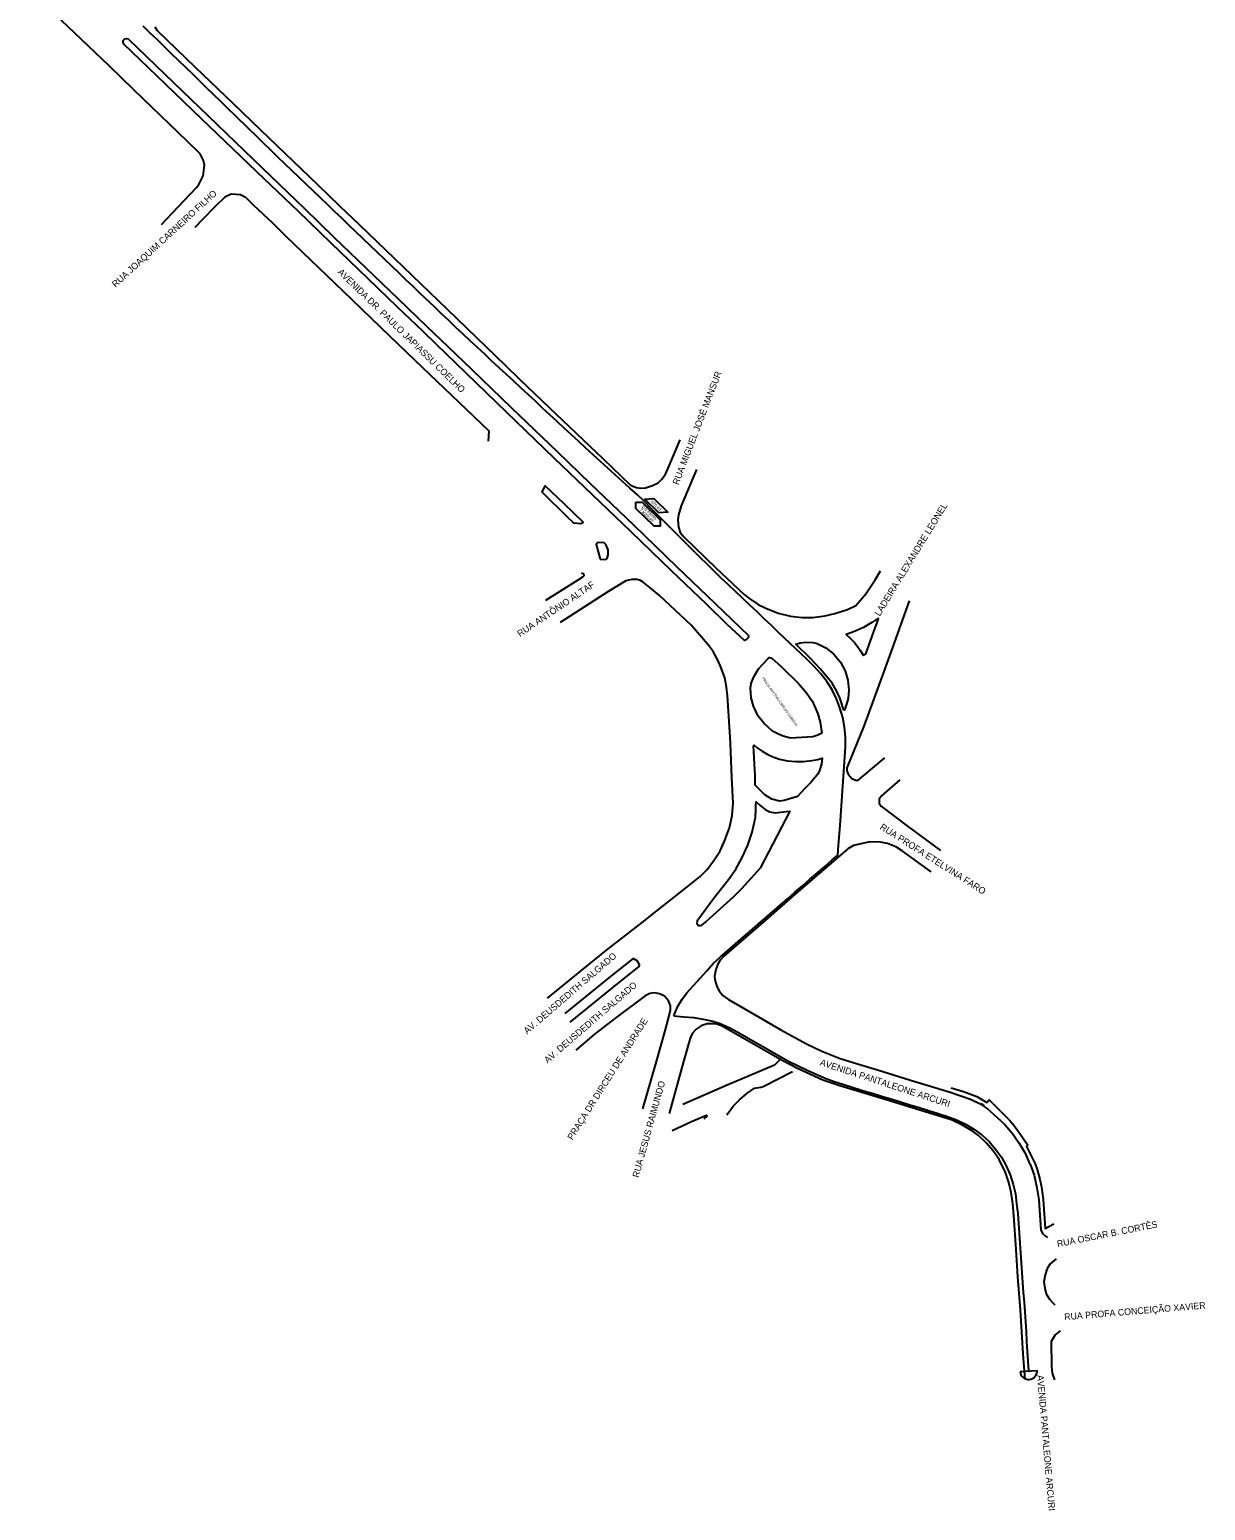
# Model space of a CAD drawing. Extents: x 656692 to 673945, y 7585994 to 7599066.
# Drawn here: x 665793 to 666966, y 7585994 to 7587471 of the extents above; entities that cross this region are included whole.
import ezdxf

# ---------------------------------------------------------------- set-up
doc = ezdxf.new("R2010")
doc.units = 0
for name, color, linetype in [('LOGRADOURO', 7, 'Continuous'), ('LOGRADOURO_TEXTO', 7, 'Continuous'), ('SIMBOLO', 7, 'Continuous'), ('TEXTO', 7, 'Continuous'), ('TUBO_PEAD_GN_63', 7, 'Continuous')]:
    doc.layers.add(name, color=color, linetype=linetype)

msp = doc.modelspace()

# ---------------------------------------------------------------- linework, layer by layer
at = {"layer": 'LOGRADOURO'}
msp.add_line((666745.5, 7586398), (666742.5, 7586400.4), dxfattribs=at)
for points in [[(665924.7, 7587277.2), (665941, 7587294.5), (665959.5, 7587314), (665962, 7587316.8), (665966.4, 7587325.6), (665967.4, 7587333.5), (665967.5, 7587336.3), (665966.7, 7587340.9), (665963.3, 7587347.4), (665950.2, 7587360.3), (665897.3, 7587411.2), (665872.5, 7587435.2), (665838.3, 7587467.8), (665793.2, 7587511.3)], [(665917.9, 7587474.3), (665920.1, 7587471), (665958.3, 7587434.1), (665995.7, 7587398.2), (666023.5, 7587371.5), (666080.2, 7587317), (666102.7, 7587295.4), (666122, 7587276.9), (666209.5, 7587192.5), (666267.8, 7587136.4), (666281.9, 7587122.8), (666311.7, 7587094.3), (666365.1, 7587043.2), (666392.3, 7587017.3), (666394.8, 7587015.9), (666398.5, 7587014.6), (666402.6, 7587014), (666407.3, 7587014.4), (666414.4, 7587016.8), (666420, 7587019.5), (666423.9, 7587023), (666427.3, 7587027.9), (666430.1, 7587034.1), (666442.1, 7587062.4)], [(665887, 7587457.1), (665886.2, 7587460.1), (665888.1, 7587462.4), (665890.2, 7587462.7), (665891.4, 7587462.1), (665928, 7587427), (665971.4, 7587385.3), (666025, 7587333.7), (666067.2, 7587293.1), (666096.7, 7587264.4), (666160.8, 7587203), (666189.4, 7587175.4), (666202.8, 7587162.7), (666234.2, 7587132.4), (666273.4, 7587094.5), (666319.7, 7587050.2), (666351.9, 7587019.2), (666395.4, 7586977.6), (666438.4, 7586935.9), (666477.1, 7586898.9), (666510.1, 7586867.1), (666510, 7586864.8), (666510, 7586864.8), (666508, 7586862.7), (666506.1, 7586862.2), (666489.3, 7586877.8), (666468.3, 7586898.3), (666433.3, 7586931.7), (666393.1, 7586970.4), (666347.1, 7587014.7), (666316.5, 7587044.1), (666269.3, 7587089.6), (666228.5, 7587128.9), (666198.9, 7587157.3), (666185.4, 7587170.7), (666160.2, 7587194.6), (666130.4, 7587223.3), (666093.8, 7587258.4), (666060.9, 7587290.3), (666027.4, 7587322.4), (665964.7, 7587382.4), (665920.2, 7587425.2), (665887, 7587457.1)], [(666250.8, 7587060.9), (666251.4, 7587070.9), (666207, 7587113.5), (666177.8, 7587141.3), (666143.9, 7587174), (666114.5, 7587202.3), (666049.1, 7587265.1), (666035.7, 7587278.3), (666016.8, 7587295.9), (666009.3, 7587303.8), (666003.6, 7587306.8), (665994.2, 7587307.3), (665987.8, 7587304.3), (665978.3, 7587295.1), (665965.9, 7587282.4), (665957.9, 7587274.1)], [(666458.4, 7587032.6), (666443.2, 7586996.4), (666440.5, 7586987.6), (666439.8, 7586982.5), (666440.4, 7586975.3), (666442, 7586970), (666446, 7586965.1), (666478, 7586934.2), (666506, 7586908), (666511.5, 7586903.6), (666519.9, 7586898), (666527.4, 7586894.3), (666539.8, 7586889.3), (666552, 7586886.4), (666563.6, 7586885), (666574.2, 7586885.1), (666586.4, 7586886.6), (666596.4, 7586888.9), (666609, 7586893), (666617.3, 7586897.1), (666627.1, 7586908.8), (666636.6, 7586922.6), (666641.9, 7586931.6)], [(666305.8, 7587008.6), (666304.4, 7587010.1), (666307.4, 7587016.4), (666326.1, 7586998.7), (666345.4, 7586980.1), (666343, 7586978.4), (666335.9, 7586979.2), (666329.1, 7586985.8), (666305.8, 7587008.6)], [(666362.3, 7586943.2), (666367.9, 7586943), (666369.3, 7586944), (666370.3, 7586947.6), (666370.3, 7586952.7), (666368, 7586958), (666366.1, 7586959.4), (666360, 7586959.7), (666358.3, 7586957.8), (666362.3, 7586943.2)], [(666340.2, 7586922.6), (666344.9, 7586925.7), (666346.2, 7586926.8), (666346, 7586928.3), (666343.5, 7586929.2)], [(666308.2, 7586902.3), (666340.2, 7586922.6), (666340.2, 7586922.6)], [(666309.6, 7586505.3), (666343.9, 7586533.3), (666368.7, 7586553.3), (666404, 7586580.8), (666418.7, 7586592.5), (666448.6, 7586616.1), (666461.9, 7586626.7), (666469.1, 7586633.7), (666476.4, 7586643.7), (666481.5, 7586651.7), (666486.3, 7586662), (666491.2, 7586675.2), (666493.9, 7586687.5), (666494.8, 7586700), (666493.6, 7586725.3), (666492.3, 7586759.6), (666490.5, 7586786.5), (666489.3, 7586806.8), (666488.3, 7586815.7), (666486.5, 7586825), (666482.4, 7586836.5), (666479.1, 7586843.7), (666474.8, 7586851.1), (666470, 7586857.8), (666453, 7586877.3), (666421.4, 7586907), (666411.9, 7586915.1), (666405, 7586920.3), (666401.8, 7586922.2), (666399.1, 7586922.8), (666393.9, 7586922.9), (666387.9, 7586921.6), (666370.9, 7586911.2), (666322.3, 7586880.1)], [(666670.3, 7586901.6), (666656.7, 7586863.4), (666645.2, 7586831.1), (666625.3, 7586776.6), (666608.4, 7586735.2), (666608.2, 7586732.2), (666609.7, 7586728.8), (666613.2, 7586724.6), (666617.1, 7586722.7), (666619.2, 7586722.6), (666625.6, 7586727.8), (666646.2, 7586745)], [(666624.9, 7586847), (666627.2, 7586848.9), (666634.8, 7586870.2), (666639.7, 7586883.8), (666639.1, 7586884.2), (666633.1, 7586880), (666624.9, 7586875.2), (666615.9, 7586871.2), (666607.5, 7586868.1), (666611.4, 7586864.8), (666616.2, 7586859.8), (666621.2, 7586852.8), (666624.9, 7586847)], [(666605.2, 7586792.6), (666601.2, 7586804.9), (666597.7, 7586812.5), (666593.6, 7586819.4), (666590.3, 7586823.7), (666581.7, 7586834), (666572.4, 7586843.7), (666557.3, 7586858.5), (666561.8, 7586859.9), (666567.4, 7586860.3), (666574.3, 7586860.2), (666578.6, 7586859.1), (666587.4, 7586854.7), (666595.1, 7586848.8), (666601.8, 7586840.6), (666606.5, 7586832), (666609.3, 7586822.5), (666610.3, 7586812.7), (666609.5, 7586804.4), (666608.1, 7586798.6), (666606, 7586792.6), (666605.2, 7586792.6)], [(666583.4, 7586769.6), (666579.5, 7586767.8), (666574.5, 7586766.1), (666552.1, 7586764.7), (666544.9, 7586766.7), (666540.2, 7586768.6), (666534.2, 7586771.8), (666525.7, 7586779.2), (666519.7, 7586786.8), (666515.1, 7586796.5), (666513, 7586805), (666512.1, 7586814.7), (666512.9, 7586819.2), (666515.4, 7586826), (666520.1, 7586833.9), (666529.5, 7586843.9), (666531.2, 7586845), (666533.6, 7586844.6), (666543.1, 7586835.7), (666560.1, 7586819.3), (666568.2, 7586810), (666574, 7586801.2), (666579.5, 7586789.1), (666581.6, 7586780.8), (666583.4, 7586769.6)], [(666515.2, 7586757.2), (666515.7, 7586757.7), (666519, 7586755.1), (666523.8, 7586751.7), (666529.4, 7586748.5), (666535.4, 7586745.8), (666541, 7586743.9), (666549, 7586742.2), (666557.3, 7586741.4), (666565.2, 7586741.3), (666573.3, 7586742.3), (666579.5, 7586743.5), (666583.7, 7586744.7), (666582.9, 7586738.7), (666580.6, 7586731.4), (666579.1, 7586728.4), (666572.3, 7586720.5), (666566.1, 7586714.3), (666559.1, 7586706.4), (666545.9, 7586702.6), (666541.1, 7586701.9), (666533.4, 7586704), (666526.6, 7586708.3), (666520.7, 7586713.9), (666516.9, 7586717.8), (666516.7, 7586727.1), (666515.2, 7586757.2)], [(666661, 7586723.1), (666642.7, 7586707.2), (666640.5, 7586703.8), (666640.5, 7586699.5), (666642.7, 7586696.6), (666668.9, 7586677), (666701.6, 7586652.6)], [(666462.4, 7586577.6), (666460.4, 7586577.5), (666458.9, 7586579.3), (666459.3, 7586582.4), (666459.7, 7586583.5), (666475.4, 7586604.8), (666490.2, 7586623.7), (666497.4, 7586634), (666503.8, 7586645.5), (666509.5, 7586658.1), (666513.7, 7586670.9), (666517.1, 7586685.7), (666517.6, 7586693.9), (666517.5, 7586698), (666517.8, 7586701.3), (666521.5, 7586698), (666526.9, 7586693.6), (666531.6, 7586691.2), (666536.7, 7586690.2), (666547.9, 7586691.5), (666551.4, 7586691.8), (666521.7, 7586635), (666521.7, 7586635), (666503.2, 7586614.3), (666494.9, 7586606.2), (666468, 7586581.8), (666462.4, 7586577.6)], [(666692.3, 7586631.5), (666663.5, 7586652.3), (666657.7, 7586656.1), (666648.7, 7586659.6), (666641.8, 7586660.9), (666631.2, 7586661.3), (666614.9, 7586657.7), (666609.3, 7586654.4), (666557.2, 7586609.5), (666527.3, 7586583.3), (666485.6, 7586547.2), (666481.9, 7586543.3), (666479.6, 7586539.4), (666477.6, 7586533.8), (666476.3, 7586527.4), (666476.5, 7586523.6), (666478.5, 7586516.9), (666480.9, 7586512.6), (666484.7, 7586508.1), (666490.3, 7586503.9), (666520.3, 7586486.6), (666542.6, 7586473.7), (666568.1, 7586459.9), (666583.4, 7586452.6), (666601.7, 7586445.1), (666618.9, 7586439.8), (666639, 7586433.7), (666671.8, 7586423.7), (666710.2, 7586411.9), (666731.6, 7586404.7), (666740.7, 7586400.3), (666748.6, 7586394.8), (666754.6, 7586389.6), (666765.8, 7586379.4), (666773.5, 7586370.4), (666780.3, 7586360.8), (666786.1, 7586350.9), (666790.2, 7586341.2), (666791.2, 7586339.7), (666795, 7586328.7), (666797.7, 7586316.2), (666799.7, 7586304.3), (666800.5, 7586293.9), (666801.9, 7586274.4), (666803.6, 7586270.5), (666806.5, 7586267.8), (666808.5, 7586266.5)], [(666332.3, 7586481.4), (666379.9, 7586520.1), (666399.6, 7586535.5), (666401.3, 7586537), (666401.5, 7586538.6), (666399.3, 7586542.6), (666395.3, 7586544.8), (666373, 7586527.3), (666326.9, 7586490)], [(666404.9, 7586394.9), (666418.5, 7586442.2), (666427, 7586472.7), (666432.4, 7586493), (666432.4, 7586497.6), (666430.5, 7586502.6), (666426.3, 7586507.2), (666421.3, 7586509.8), (666416.4, 7586510.7), (666411.7, 7586510), (666407.1, 7586507.8), (666378.2, 7586486.1), (666356.5, 7586469.3), (666337.9, 7586453.5)], [(666786.2, 7586125), (666784.3, 7586150.5), (666781.5, 7586194.4), (666779, 7586227.3), (666777.1, 7586254.7), (666774.8, 7586288.7), (666773.7, 7586300.1), (666772.2, 7586311.5), (666769.9, 7586321.4), (666766.5, 7586331.6), (666760.1, 7586344.4), (666753.9, 7586353.3), (666747.3, 7586361.2), (666739.6, 7586368.5), (666734.2, 7586372.2), (666723.7, 7586378.8), (666713.2, 7586383.5), (666707, 7586385.6), (666643.3, 7586405.3), (666601.4, 7586417.8), (666584.3, 7586423.7), (666567.6, 7586431.3), (666559.9, 7586435), (666544.5, 7586442.7), (666529.9, 7586451.1), (666483.2, 7586477.9), (666478.7, 7586479.5), (666475.2, 7586479.8), (666469.1, 7586479.6), (666463, 7586477.9), (666457.9, 7586474.3), (666454.4, 7586470.5), (666452.1, 7586465.5), (666445.4, 7586442.2), (666431, 7586390.4)], [(666541.4, 7586443.9), (666536, 7586438.6), (666489, 7586418.6), (666444.8, 7586399.4)], [(666488.7, 7586389.1), (666495, 7586397.6), (666501.1, 7586404.1), (666508.4, 7586410.2), (666516.1, 7586415.5), (666522.6, 7586416.5), (666524.7, 7586417.1), (666554.2, 7586432.2)], [(666712.4, 7586416), (666724.7, 7586412.1), (666738, 7586407.3), (666747.8, 7586401.2), (666750.2, 7586403.9), (666770.5, 7586383.6), (666775, 7586378.8), (666780.8, 7586370.3), (666788.8, 7586358.7), (666787.4, 7586357.4), (666796, 7586340.2), (666798.1, 7586334.5), (666800.7, 7586324.8), (666802.3, 7586316.7), (666804.1, 7586304.5), (666806.2, 7586275.7), (666814.6, 7586280.1)], [(666433.9, 7586373.5), (666453.4, 7586382.3), (666468.4, 7586388.8), (666469, 7586387.8), (666465.6, 7586384.6)], [(666817.2, 7586245.4), (666811.1, 7586240.4), (666808.2, 7586235.8), (666806, 7586229.5), (666804.9, 7586222.3), (666806, 7586214.2), (666807.3, 7586209.8), (666810.5, 7586205.1), (666813.6, 7586201.3), (666815.7, 7586199.3)], [(666821.1, 7586173.5), (666816, 7586169.5), (666812.2, 7586163), (666812.5, 7586138), (666813.1, 7586131.4), (666815.5, 7586124.6)]]:
    msp.add_lwpolyline(points, dxfattribs=at)
at = {"layer": 'SIMBOLO'}
msp.add_lwpolyline([(666397.9, 7587000.1), (666404.1, 7587000.2), (666422.1, 7586982.5), (666422.2, 7586976.3), (666416, 7586976.3), (666397.9, 7586993.9), (666397.9, 7587000.1)], dxfattribs=at)
msp.add_lwpolyline([(666420.6, 7586989.6), (666406.9, 7587003), (666415.9, 7587003.7), (666429.6, 7586990.2)], close=True, dxfattribs=at)
at = {"layer": 'TUBO_PEAD_GN_63'}
msp.add_line((666781.1, 7586133), (666798.1, 7586133.9), dxfattribs=at)
for points in [[(666599.4, 7586648.1), (666600.1, 7586657.9), (666601.5, 7586677.5), (666602.2, 7586687.3), (666602.9, 7586697.1), (666603.6, 7586707), (666604.3, 7586716.8), (666605, 7586726.6), (666606.4, 7586746.2), (666607, 7586756.1), (666607, 7586765.9), (666606, 7586775.7), (666604.2, 7586785.4), (666601.4, 7586794.8), (666597.9, 7586804), (666593.5, 7586812.8), (666588.3, 7586821.2), (666582.4, 7586829), (666575.8, 7586836.3), (666568.7, 7586843.1), (666540.2, 7586870.2), (666533, 7586877), (666525.9, 7586883.8), (666518.7, 7586890.6), (666511.6, 7586897.3), (666497.3, 7586910.9), (666490.2, 7586917.7), (666483, 7586924.4), (666475.9, 7586931.2), (666468.9, 7586938.1), (666461.9, 7586945), (666454.9, 7586951.9), (666447.9, 7586958.9), (666440.9, 7586965.8), (666433.9, 7586972.8), (666427, 7586979.8), (666420.1, 7586986.8), (666413.2, 7586993.8), (666406.3, 7587000.8), (666399.3, 7587007.7), (666391.9, 7587014.2), (666377.2, 7587027.3), (666369.9, 7587033.9), (666362.6, 7587040.5), (666348.1, 7587053.9), (666340.9, 7587060.6), (666333.7, 7587067.3), (666326.5, 7587073.9), (666319.3, 7587080.6), (666312.1, 7587087.3), (666304.8, 7587094), (666297.6, 7587100.7), (666290.4, 7587107.4), (666283.2, 7587114.1), (666276, 7587120.8), (666261.6, 7587134.2), (666254.3, 7587140.9), (666247.1, 7587147.6), (666239.9, 7587154.3), (666232.7, 7587161), (666225.5, 7587167.7), (666218.3, 7587174.4), (666211.2, 7587181.2), (666204.1, 7587188), (666196.9, 7587194.8), (666182.7, 7587208.4), (666175.6, 7587215.2), (666168.5, 7587222), (666161.4, 7587228.8), (666147.2, 7587242.4), (666140.1, 7587249.2), (666125.9, 7587262.9), (666118.7, 7587269.7), (666111.6, 7587276.5), (666104.5, 7587283.3), (666097.4, 7587290.1), (666090.3, 7587296.9), (666083.2, 7587303.7), (666069, 7587317.3), (666061.9, 7587324.1), (666047.7, 7587337.7), (666040.5, 7587344.6), (666033.5, 7587351.4), (666026.4, 7587358.3), (666019.4, 7587365.1), (666012.3, 7587372), (665998.2, 7587385.7), (665991.1, 7587392.6), (665984.1, 7587399.4), (665977, 7587406.3), (665970, 7587413.1), (665955.8, 7587426.9), (665934.7, 7587447.4), (665920.6, 7587461.2), (665913.5, 7587468), (665906.4, 7587474.9)], [(666435.8, 7586487.6), (666439.4, 7586496.7), (666444, 7586504.5), (666448.7, 7586510.6), (666448.7, 7586510.6), (666455.3, 7586517.9), (666461.9, 7586525.2), (666468.5, 7586532.5), (666475.1, 7586539.8), (666482.2, 7586546.5), (666489.7, 7586553), (666497.1, 7586559.4), (666504.6, 7586565.8), (666512, 7586572.3), (666519.5, 7586578.7), (666526.9, 7586585.2), (666534.3, 7586591.6), (666541.7, 7586598.2), (666549.2, 7586604.5), (666556.5, 7586611.1), (666564.1, 7586617.4), (666571.4, 7586624), (666578.9, 7586630.3), (666586.3, 7586636.8), (666593.8, 7586643.2), (666599.4, 7586648.1)], [(666435.8, 7586487.6), (666445.6, 7586486.8), (666455.4, 7586486.1), (666465.1, 7586484.5), (666474.7, 7586482.3), (666482, 7586480.1), (666491, 7586476.1), (666499.6, 7586471.4), (666508.2, 7586466.5), (666516.7, 7586461.6), (666525.2, 7586456.7), (666533.8, 7586451.8), (666542.3, 7586446.9), (666550.9, 7586442.2), (666559.8, 7586437.8), (666568.6, 7586433.6), (666577.6, 7586429.4), (666586.6, 7586425.6), (666595.8, 7586422.2), (666605.2, 7586419.1), (666614.6, 7586416.2), (666624, 7586413.4), (666633.5, 7586410.6), (666642.9, 7586407.7), (666652.3, 7586404.9), (666661.7, 7586402), (666671.1, 7586399.1), (666680.5, 7586396.2), (666689.9, 7586393.3), (666699.3, 7586390.4), (666708.7, 7586387.4), (666717.8, 7586384.1), (666726.8, 7586379.7), (666735.1, 7586374.7), (666743.1, 7586368.8), (666750.4, 7586362.3), (666756.6, 7586354.6), (666762.4, 7586346.7), (666767.2, 7586338), (666771.2, 7586329.1), (666774.1, 7586319.6), (666776.4, 7586310.1), (666777.6, 7586300.3), (666778.7, 7586290.6), (666779.4, 7586280.7), (666780.1, 7586270.9), (666780.7, 7586261), (666781.4, 7586251.2), (666782.1, 7586241.4), (666782.8, 7586231.6), (666783.5, 7586221.8), (666784.2, 7586211.9), (666785, 7586202.1), (666785.7, 7586192.4), (666786.4, 7586182.5), (666787, 7586172.7), (666787.6, 7586162.9), (666788.2, 7586153), (666788.9, 7586143.2), (666789.6, 7586133.5)]]:
    msp.add_lwpolyline(points, dxfattribs=at)
msp.add_arc((666789.6, 7586133.5), 8.51, 183.0134, 3.0134, dxfattribs=at)

# ---------------------------------------------------------------- texts
at = {"layer": 'LOGRADOURO_TEXTO'}
for s, height, rotation, p in [('RUA JOAQUIM CARNEIRO FILHO', 6.562, 42.5662, (665878.9, 7587213.9)), ('AVENIDA DR. PAULO JAPIASSU COELHO', 6.562, 315.8153, (666099.9, 7587228.9)), ('RUA MIGUEL JOSÉ MANSUR', 6.562, 68.9386, (666440.3, 7587016.8)), ('LADEIRA ALEXANDRE LEONEL', 6.562, 58.5728, (666641.1, 7586885.8)), ('RUA ANTÔNIO ALTAF', 6.562, 34.0975, (666282.3, 7586865.4)), ('PRAÇA ANTÔNIO CARLOS SARAÍVA', 2.461, 305.2718, (666523.4, 7586824.4)), ('RUA PROFA ETELVINA FARO', 6.562, 327.4671, (666640.6, 7586674.5)), ('AV. DEUSDEDITH SALGADO', 6.562, 40.7132, (666289.4, 7586469.2)), ('AV. DEUSDEDITH SALGADO', 6.562, 40.7132, (666309.8, 7586440.1)), ('PRAÇA DR DIRCEU DE ANDRADE', 6.562, 57.7456, (666334.6, 7586363.3)), ('AVENIDA PANTALEONE ARCURI', 6.562, 341.9348, (666580.8, 7586438.6)), ('RUA JESUS RAIMUNDO', 6.562, 74.5137, (666400.6, 7586325.9)), ('RUA OSCAR B. CORTÊS', 6.562, 11.2974, (666818.6, 7586256.9)), ('RUA PROFA CONCEIÇÃO XAVIER', 6.562, 4.7419, (666825.4, 7586184.1)), ('AVENIDA PANTALEONE ARCURI', 6.562, 274.8903, (666798, 7586129.2))]:
    msp.add_text(s, height=height, rotation=rotation, dxfattribs=at).set_placement(p)
at = {"layer": 'TEXTO'}
for s, p in [('626,63', (666412.6, 7587000)), ('7 Kgf/cm²', (666401.3, 7586992.1)), ('DN 63mm', (666403.6, 7586995.2))]:
    msp.add_text(s, height=3, rotation=315.724, dxfattribs=at).set_placement(p)

doc.saveas('drawing.dxf')
